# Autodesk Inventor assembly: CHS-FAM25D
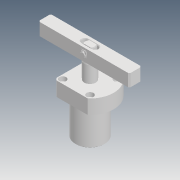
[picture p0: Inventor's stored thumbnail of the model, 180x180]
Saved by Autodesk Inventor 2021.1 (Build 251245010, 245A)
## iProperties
Created: 2019-04
Part Number: CHS-FAM25D
Description: STEP AP203
Document SubType Name: Assembly
Designer: user
Title: chs-fam25d_asm.STEP
Revision Number: ÈÎºÎ
Sending System: SolidWorks 2017
Preprocessor: SwSTEP 2.0
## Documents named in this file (6)
- D:\Vault_2016\Projekty\Clamptek\Hydraulic\CHS\CHS-25\Inventor\CHS-FAM25D\CHS-FAM25D.iam
- D:\Vault_2016\Projekty\Clamptek\Hydraulic\CHS\CHS-25\Inventor\CHS-FAM25D\CHS-FAM25BT.ipt
- D:\Vault_2016\Projekty\Clamptek\Hydraulic\CHS\CHS-25\Inventor\CHS-FAM25D\CHS-25D-02_2.ipt
- D:\Vault_2016\Projekty\Clamptek\Hydraulic\CHS\CHS-25\Inventor\CHS-FAM25D\CHS-25D-01_2.ipt
- D:\Vault_2016\Projekty\Clamptek\Hydraulic\CHS\CHS-25\Inventor\CHS-FAM25D\Öá8µ²È¦.ipt
- D:\Vault_2016\Projekty\Clamptek\Hydraulic\CHS\CHS-25\Inventor\CHS-FAM25D\Xiao.ipt
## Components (6 placed, 6 different names)
1. CHS-FAM25BT_1
2. CHS-25D-02_2_2
3. CHS-25D-01_2_3
4. Öá8µ²È¦_4
5. Xiao_5
6. Öá8µ²È¦_6
